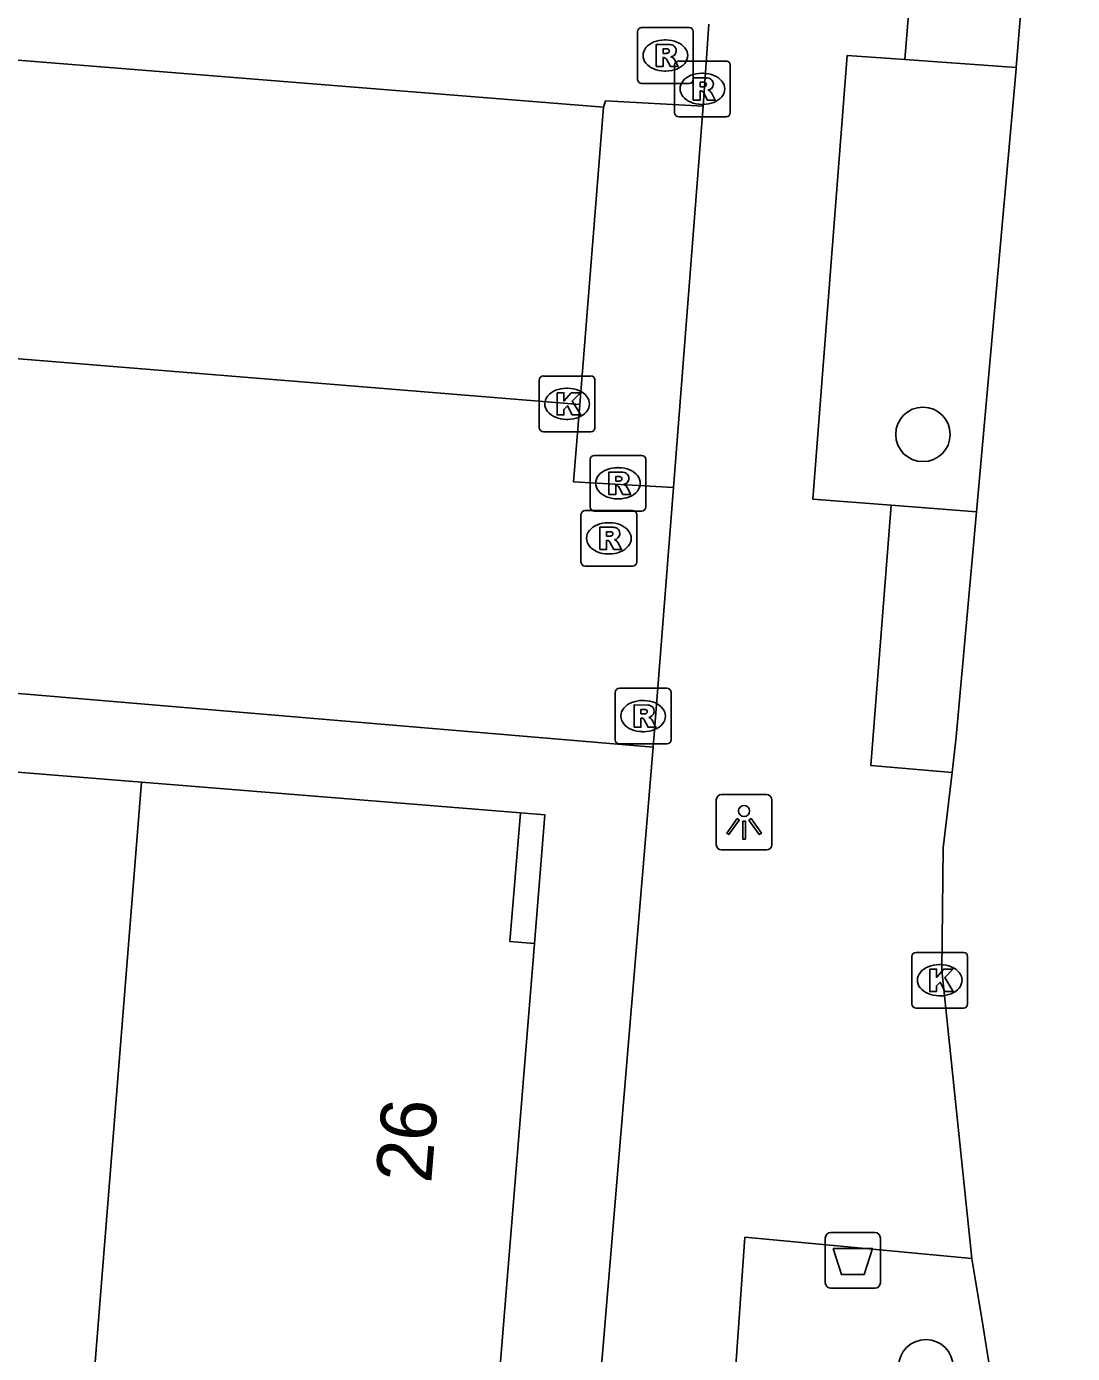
# Model space of a CAD drawing. Extents: x 159961 to 160856, y 382704 to 383353.
# Drawn here: x 160570.73 to 160589.51, y 383225.38 to 383249.21 of the extents above; entities that cross this region are included whole.
import ezdxf

# ---------------------------------------------------------------- set-up
doc = ezdxf.new("R2010")
doc.units = 0
for name, color, linetype in [('IMGEO_Afvalbak', 7, 'Continuous'), ('IMGEO_Boom', 7, 'Continuous'), ('IMGEO_Groenvoorziening', 7, 'Continuous'), ('IMGEO_Kolk', 7, 'Continuous'), ('IMGEO_Lichtpunt', 7, 'Continuous'), ('IMGEO_Pand', 7, 'Continuous'), ('IMGEO_Pand_nummerreeks', 7, 'Continuous'), ('IMGEO_Pand_overbouw', 7, 'Continuous'), ('IMGEO_Parkeervlak_open', 7, 'Continuous'), ('IMGEO_Rijbaan_lokaal_open', 7, 'Continuous'), ('IMGEO_Rioolput', 7, 'Continuous'), ('IMGEO_Voetpad_open', 7, 'Continuous')]:
    doc.layers.add(name, color=color, linetype=linetype)

msp = doc.modelspace()

# ---------------------------------------------------------------- linework, layer by layer
at = {"layer": 'IMGEO_Afvalbak'}
for p, q in [((160585.07, 383226.656), (160585.07, 383227.456)), ((160585.07, 383227.456), (160585.07, 383226.656)), ((160585.17, 383227.556), (160585.96, 383227.556)), ((160585.96, 383227.556), (160585.17, 383227.556)), ((160586.06, 383227.456), (160586.06, 383226.656)), ((160586.06, 383226.656), (160586.06, 383227.456)), ((160585.96, 383226.556), (160585.17, 383226.556)), ((160585.17, 383226.556), (160585.96, 383226.556))]:
    msp.add_line(p, q, dxfattribs=at)
msp.add_lwpolyline([(160585.213, 383227.27), (160585.917, 383227.27), (160585.768, 383226.8), (160585.362, 383226.8), (160585.213, 383227.27)], dxfattribs=at)
for centre, start, end in [((160585.17, 383227.456), 90, 180), ((160585.17, 383227.456), 90, 180), ((160585.96, 383227.456), 0, 90), ((160585.96, 383227.456), 360, 90), ((160585.17, 383226.656), 180, 270), ((160585.17, 383226.656), 180, 270), ((160585.96, 383226.656), 270, 0), ((160585.96, 383226.656), 270, 0)]:
    msp.add_arc(centre, 0.1, start, end, dxfattribs=at)
at = {"layer": 'IMGEO_Boom'}
for centre in [(160586.823, 383241.888), (160586.876, 383225.145)]:
    msp.add_circle(centre, 0.489, dxfattribs=at)
at = {"layer": 'IMGEO_Groenvoorziening'}
msp.add_lwpolyline([(160586.496, 383248.621), (160588.498, 383248.477)], dxfattribs=at)
at = {"layer": 'IMGEO_Kolk'}
for p, q in [((160579.934, 383242.011), (160579.934, 383242.863)), ((160580.009, 383242.937), (160580.861, 383242.937)), ((160580.935, 383242.863), (160580.935, 383242.011)), ((160580.422, 383242.717), (160580.447, 383242.717)), ((160580.445, 383242.157), (160580.42, 383242.157)), ((160580.861, 383241.937), (160580.009, 383241.937)), ((160586.699, 383232.587), (160587.551, 383232.587)), ((160586.624, 383231.661), (160586.624, 383232.513)), ((160587.112, 383232.367), (160587.137, 383232.367)), ((160587.625, 383232.513), (160587.625, 383231.661)), ((160587.135, 383231.807), (160587.11, 383231.807)), ((160587.551, 383231.587), (160586.699, 383231.587))]:
    msp.add_line(p, q, dxfattribs=at)
for points in [[(160579.934, 383242.011), (160579.934, 383242.863)], [(160580.009, 383242.937), (160580.861, 383242.937)], [(160580.935, 383242.863), (160580.935, 383242.011)], [(160580.255, 383242.637), (160580.378, 383242.637), (160580.378, 383242.486), (160580.508, 383242.637), (160580.672, 383242.637), (160580.526, 383242.486), (160580.679, 383242.237), (160580.527, 383242.237), (160580.442, 383242.401), (160580.378, 383242.334), (160580.378, 383242.237), (160580.255, 383242.237), (160580.255, 383242.637)], [(160580.861, 383241.937), (160580.009, 383241.937)], [(160586.699, 383232.587), (160587.551, 383232.587)], [(160586.624, 383231.661), (160586.624, 383232.513)], [(160587.625, 383232.513), (160587.625, 383231.661)], [(160586.945, 383232.287), (160587.068, 383232.287), (160587.068, 383232.136), (160587.198, 383232.287), (160587.362, 383232.287), (160587.216, 383232.136), (160587.369, 383231.887), (160587.217, 383231.887), (160587.132, 383232.051), (160587.068, 383231.984), (160587.068, 383231.887), (160586.945, 383231.887), (160586.945, 383232.287)], [(160587.551, 383231.587), (160586.699, 383231.587)]]:
    msp.add_lwpolyline(points, dxfattribs=at)
for centre, start, end in [((160580.011, 383242.861), 91.552, 178.448), ((160580.011, 383242.861), 91.552, 178.448), ((160580.859, 383242.861), 1.552, 88.448), ((160580.859, 383242.861), 1.552, 88.448), ((160580.011, 383242.013), 181.552, 268.448), ((160580.011, 383242.013), 181.552, 268.448), ((160580.859, 383242.013), 271.552, 358.448), ((160580.859, 383242.013), 271.552, 358.448), ((160586.701, 383232.511), 91.552, 178.448), ((160586.701, 383232.511), 91.552, 178.448), ((160587.549, 383232.511), 1.552, 88.448), ((160587.549, 383232.511), 1.552, 88.448), ((160586.701, 383231.663), 181.552, 268.448), ((160586.701, 383231.663), 181.552, 268.448), ((160587.549, 383231.663), 271.552, 358.448), ((160587.549, 383231.663), 271.552, 358.448)]:
    msp.add_arc(centre, 0.0765, start, end, dxfattribs=at)
for centre, major_axis, ratio, start_param, end_param in [((160580.421, 383242.437), (-0.387, 0.002), 0.722429, 4.712389, 7.853982), ((160580.446, 383242.437), (-0.39, 0.002), 0.717154, 1.570796, 4.712389), ((160587.111, 383232.087), (-0.387, 0.002), 0.722429, 4.712389, 7.853982), ((160587.136, 383232.087), (-0.39, 0.002), 0.717154, 1.570796, 4.712389)]:
    msp.add_ellipse(centre, major_axis=major_axis, ratio=ratio, start_param=start_param, end_param=end_param, dxfattribs=at)
at = {"layer": 'IMGEO_Lichtpunt'}
for p, q in [((160584.015, 383235.423), (160583.207, 383235.423)), ((160584.015, 383235.423), (160583.207, 383235.423)), ((160583.113, 383235.328), (160583.113, 383234.521)), ((160583.113, 383235.328), (160583.113, 383234.521)), ((160584.109, 383234.521), (160584.109, 383235.328)), ((160584.109, 383234.521), (160584.109, 383235.328)), ((160583.207, 383234.427), (160584.015, 383234.427)), ((160583.207, 383234.427), (160584.015, 383234.427))]:
    msp.add_line(p, q, dxfattribs=at)
for points in [[(160583.487, 383234.992), (160583.526, 383234.964), (160583.338, 383234.702), (160583.3, 383234.729), (160583.487, 383234.992)], [(160583.589, 383234.944), (160583.636, 383234.944), (160583.636, 383234.622), (160583.589, 383234.622), (160583.589, 383234.944)], [(160583.699, 383234.964), (160583.737, 383234.991), (160583.924, 383234.729), (160583.885, 383234.701), (160583.699, 383234.964)]]:
    msp.add_lwpolyline(points, dxfattribs=at)
msp.add_circle((160583.612, 383235.126), 0.0994, dxfattribs=at)
for centre, start, end in [((160583.207, 383235.328), 90, 180), ((160583.207, 383235.328), 90, 180), ((160584.015, 383235.328), 0, 90), ((160584.015, 383235.328), 0, 90), ((160583.207, 383234.521), 180, 270), ((160583.207, 383234.521), 180, 270), ((160584.015, 383234.521), 270, 0), ((160584.015, 383234.521), 270, 360)]:
    msp.add_arc(centre, 0.0946, start, end, dxfattribs=at)
at = {"layer": 'IMGEO_Pand'}
for points in [[(160571.829, 383223.583), (160572.795, 383235.644)], [(160572.795, 383235.644), (160574.348, 383235.518), (160579.597, 383235.091), (160579.407, 383232.783), (160579.849, 383232.745), (160579.226, 383225.088), (160578.784, 383225.124), (160578.614, 383223.032)]]:
    msp.add_lwpolyline(points, dxfattribs=at)
at = {"layer": 'IMGEO_Pand_overbouw'}
msp.add_lwpolyline([(160579.849, 383232.745), (160580.036, 383235.055), (160579.597, 383235.091), (160579.407, 383232.783)], close=True, dxfattribs=at)
at = {"layer": 'IMGEO_Parkeervlak_open'}
msp.add_lwpolyline([(160581.09, 383247.766), (160580.663, 383242.423)], dxfattribs=at)
at = {"layer": 'IMGEO_Rijbaan_lokaal_open'}
for points in [[(160589.508, 383260.177), (160588.952, 383254.011), (160588.498, 383248.477)], [(160588.498, 383248.477), (160588.496, 383248.453), (160587.783, 383240.496)], [(160568.236, 383243.436), (160580.663, 383242.423)], [(160581.98, 383236.274), (160570.304, 383237.257), (160570.385, 383238.185), (160570.07, 383238.212), (160565.614, 383238.538), (160510.942, 383242.971)], [(160580.663, 383242.423), (160580.551, 383241.038), (160582.344, 383240.936)], [(160582.344, 383240.936), (160581.98, 383236.274)], [(160587.783, 383240.496), (160587.421, 383236.457), (160587.346, 383235.819)], [(160587.701, 383227.093), (160587.161, 383232.265), (160587.185, 383234.463), (160587.346, 383235.819)], [(160588.179, 383224.135), (160587.897, 383225.898), (160587.701, 383227.093)]]:
    msp.add_lwpolyline(points, dxfattribs=at)
at = {"layer": 'IMGEO_Rioolput'}
for p, q in [((160581.698, 383248.266), (160581.698, 383249.118)), ((160581.773, 383249.192), (160582.625, 383249.192)), ((160582.699, 383249.118), (160582.699, 383248.266)), ((160582.186, 383248.972), (160582.211, 383248.972)), ((160582.438, 383248.593), (160583.29, 383248.593)), ((160582.209, 383248.412), (160582.184, 383248.412)), ((160582.363, 383247.667), (160582.363, 383248.519)), ((160582.851, 383248.373), (160582.876, 383248.373)), ((160583.364, 383248.519), (160583.364, 383247.667)), ((160582.625, 383248.192), (160581.773, 383248.192)), ((160582.874, 383247.813), (160582.849, 383247.813)), ((160583.29, 383247.593), (160582.438, 383247.593)), ((160580.847, 383240.585), (160580.847, 383241.437)), ((160580.922, 383241.511), (160581.774, 383241.511)), ((160581.848, 383241.437), (160581.848, 383240.585)), ((160581.335, 383241.291), (160581.36, 383241.291)), ((160581.358, 383240.731), (160581.333, 383240.731)), ((160580.683, 383239.596), (160580.683, 383240.448)), ((160580.758, 383240.522), (160581.61, 383240.522)), ((160581.774, 383240.511), (160580.922, 383240.511)), ((160581.684, 383240.448), (160581.684, 383239.596)), ((160581.171, 383240.302), (160581.196, 383240.302)), ((160581.194, 383239.742), (160581.169, 383239.742)), ((160581.61, 383239.522), (160580.758, 383239.522)), ((160581.374, 383237.33), (160582.226, 383237.33)), ((160581.299, 383236.404), (160581.299, 383237.256)), ((160581.787, 383237.11), (160581.812, 383237.11)), ((160582.3, 383237.256), (160582.3, 383236.404)), ((160581.81, 383236.55), (160581.785, 383236.55)), ((160582.226, 383236.33), (160581.374, 383236.33))]:
    msp.add_line(p, q, dxfattribs=at)
for points in [[(160581.698, 383248.266), (160581.698, 383249.118)], [(160581.773, 383249.192), (160582.625, 383249.192)], [(160582.699, 383249.118), (160582.699, 383248.266)], [(160582.287, 383248.89), (160582.035, 383248.892), (160582.035, 383248.492)], [(160582.213, 383248.811), (160582.159, 383248.811), (160582.159, 383248.73)], [(160582.035, 383248.492), (160582.159, 383248.492), (160582.159, 383248.654), (160582.17, 383248.654)], [(160582.159, 383248.73), (160582.211, 383248.73)], [(160582.217, 383248.625), (160582.288, 383248.492), (160582.428, 383248.492), (160582.363, 383248.618)], [(160582.438, 383248.593), (160583.29, 383248.593)], [(160582.363, 383247.667), (160582.363, 383248.519)], [(160582.952, 383248.291), (160582.7, 383248.293), (160582.7, 383247.893)], [(160583.364, 383248.519), (160583.364, 383247.667)], [(160582.625, 383248.192), (160581.773, 383248.192)], [(160582.7, 383247.893), (160582.824, 383247.893), (160582.824, 383248.055), (160582.835, 383248.055)], [(160582.878, 383248.212), (160582.824, 383248.212), (160582.824, 383248.131)], [(160582.824, 383248.131), (160582.876, 383248.131)], [(160582.882, 383248.026), (160582.953, 383247.893), (160583.093, 383247.893), (160583.028, 383248.019)], [(160583.29, 383247.593), (160582.438, 383247.593)], [(160580.847, 383240.585), (160580.847, 383241.437)], [(160580.922, 383241.511), (160581.774, 383241.511)], [(160581.848, 383241.437), (160581.848, 383240.585)], [(160581.436, 383241.209), (160581.184, 383241.211), (160581.184, 383240.811)], [(160581.184, 383240.811), (160581.308, 383240.811), (160581.308, 383240.973), (160581.319, 383240.973)], [(160581.362, 383241.13), (160581.308, 383241.13), (160581.308, 383241.049)], [(160581.308, 383241.049), (160581.36, 383241.049)], [(160581.366, 383240.944), (160581.437, 383240.811), (160581.577, 383240.811), (160581.512, 383240.937)], [(160580.683, 383239.596), (160580.683, 383240.448)], [(160580.758, 383240.522), (160581.61, 383240.522)], [(160581.774, 383240.511), (160580.922, 383240.511)], [(160581.684, 383240.448), (160581.684, 383239.596)], [(160581.272, 383240.22), (160581.02, 383240.222), (160581.02, 383239.822)], [(160581.02, 383239.822), (160581.144, 383239.822), (160581.144, 383239.984), (160581.155, 383239.984)], [(160581.198, 383240.141), (160581.144, 383240.141), (160581.144, 383240.06)], [(160581.144, 383240.06), (160581.196, 383240.06)], [(160581.202, 383239.955), (160581.273, 383239.822), (160581.413, 383239.822), (160581.348, 383239.948)], [(160581.61, 383239.522), (160580.758, 383239.522)], [(160581.374, 383237.33), (160582.226, 383237.33)], [(160581.299, 383236.404), (160581.299, 383237.256)], [(160582.3, 383237.256), (160582.3, 383236.404)], [(160581.888, 383237.028), (160581.636, 383237.03), (160581.636, 383236.63)], [(160581.814, 383236.949), (160581.76, 383236.949), (160581.76, 383236.868)], [(160581.76, 383236.868), (160581.812, 383236.868)], [(160581.636, 383236.63), (160581.76, 383236.63), (160581.76, 383236.792), (160581.771, 383236.792)], [(160581.818, 383236.763), (160581.889, 383236.63), (160582.029, 383236.63), (160581.964, 383236.756)], [(160582.226, 383236.33), (160581.374, 383236.33)]]:
    msp.add_lwpolyline(points, dxfattribs=at)
for centre, radius, start, end in [((160581.775, 383249.116), 0.0765, 91.552, 178.448), ((160581.775, 383249.116), 0.0765, 91.552, 178.448), ((160582.623, 383249.116), 0.0765, 1.552, 88.448), ((160582.623, 383249.116), 0.0765, 1.552, 88.448), ((160582.219, 383248.715), 0.0964, 77.0061, 93.1865), ((160582.233, 383248.772), 0.0378, 276.6634, 79.6772), ((160582.286, 383248.78), 0.109, 350.3612, 89.416), ((160582.169, 383248.601), 0.0533, 26.0293, 88.6989), ((160582.195, 383248.919), 0.19, 274.7715, 282.9687), ((160582.284, 383248.78), 0.112, 277.5842, 350.9817), ((160582.268, 383248.565), 0.108, 29.5134, 73.7905), ((160582.44, 383248.517), 0.0765, 91.552, 178.448), ((160582.44, 383248.517), 0.0765, 91.552, 178.448), ((160583.288, 383248.517), 0.0765, 1.552, 88.448), ((160583.288, 383248.517), 0.0765, 1.552, 88.448), ((160582.951, 383248.181), 0.109, 350.3612, 89.416), ((160581.775, 383248.268), 0.0765, 181.552, 268.448), ((160581.775, 383248.268), 0.0765, 181.552, 268.448), ((160582.623, 383248.268), 0.0765, 271.552, 358.448), ((160582.623, 383248.268), 0.0765, 271.552, 358.448), ((160582.834, 383248.002), 0.0533, 26.0293, 88.6989), ((160582.86, 383248.32), 0.19, 274.7715, 282.9687), ((160582.884, 383248.116), 0.0964, 77.0061, 93.1865), ((160582.898, 383248.173), 0.0378, 276.6634, 79.6772), ((160582.949, 383248.181), 0.112, 277.5842, 350.9817), ((160582.933, 383247.966), 0.108, 29.5134, 73.7905), ((160582.44, 383247.669), 0.0765, 181.552, 268.448), ((160582.44, 383247.669), 0.0765, 181.552, 268.448), ((160583.288, 383247.669), 0.0765, 271.552, 358.448), ((160583.288, 383247.669), 0.0765, 271.552, 358.448), ((160580.924, 383241.435), 0.0765, 91.552, 178.448), ((160580.924, 383241.435), 0.0765, 91.552, 178.448), ((160581.772, 383241.435), 0.0765, 1.552, 88.448), ((160581.772, 383241.435), 0.0765, 1.552, 88.448), ((160581.435, 383241.099), 0.109, 350.3612, 89.416), ((160581.318, 383240.92), 0.0533, 26.0293, 88.6989), ((160581.344, 383241.238), 0.19, 274.7715, 282.9687), ((160581.368, 383241.034), 0.0964, 77.0061, 93.1865), ((160581.382, 383241.091), 0.0378, 276.6634, 79.6772), ((160581.433, 383241.099), 0.112, 277.5842, 350.9817), ((160581.417, 383240.884), 0.108, 29.5134, 73.7905), ((160580.76, 383240.446), 0.0765, 91.552, 178.448), ((160580.76, 383240.446), 0.0765, 91.552, 178.448), ((160580.924, 383240.587), 0.0765, 181.552, 268.448), ((160580.924, 383240.587), 0.0765, 181.552, 268.448), ((160581.608, 383240.446), 0.0765, 1.552, 88.448), ((160581.608, 383240.446), 0.0765, 1.552, 88.448), ((160581.772, 383240.587), 0.0765, 271.552, 358.448), ((160581.772, 383240.587), 0.0765, 271.552, 358.448), ((160581.271, 383240.11), 0.109, 350.3612, 89.416), ((160581.154, 383239.931), 0.0533, 26.0293, 88.6989), ((160581.18, 383240.249), 0.19, 274.7715, 282.9687), ((160581.204, 383240.045), 0.0964, 77.0061, 93.1865), ((160581.218, 383240.102), 0.0378, 276.6634, 79.6772), ((160581.269, 383240.11), 0.112, 277.5842, 350.9817), ((160581.253, 383239.895), 0.108, 29.5134, 73.7905), ((160580.76, 383239.598), 0.0765, 181.552, 268.448), ((160580.76, 383239.598), 0.0765, 181.552, 268.448), ((160581.608, 383239.598), 0.0765, 271.552, 358.448), ((160581.608, 383239.598), 0.0765, 271.552, 358.448), ((160581.376, 383237.254), 0.0765, 91.552, 178.448), ((160581.376, 383237.254), 0.0765, 91.552, 178.448), ((160582.224, 383237.254), 0.0765, 1.552, 88.448), ((160582.224, 383237.254), 0.0765, 1.552, 88.448), ((160581.796, 383237.057), 0.19, 274.7715, 282.9687), ((160581.82, 383236.853), 0.0964, 77.0061, 93.1865), ((160581.834, 383236.91), 0.0378, 276.6634, 79.6772), ((160581.887, 383236.918), 0.109, 350.3612, 89.416), ((160581.885, 383236.918), 0.112, 277.5842, 350.9817), ((160581.77, 383236.739), 0.0533, 26.0293, 88.6989), ((160581.869, 383236.703), 0.108, 29.5134, 73.7905), ((160581.376, 383236.406), 0.0765, 181.552, 268.448), ((160581.376, 383236.406), 0.0765, 181.552, 268.448), ((160582.224, 383236.406), 0.0765, 271.552, 358.448), ((160582.224, 383236.406), 0.0765, 271.552, 358.448)]:
    msp.add_arc(centre, radius, start, end, dxfattribs=at)
for centre, major_axis, ratio, start_param, end_param in [((160582.185, 383248.692), (-0.387, 0.002), 0.722429, 4.712389, 7.853982), ((160582.21, 383248.692), (-0.39, 0.002), 0.717154, 1.570796, 4.712389), ((160582.85, 383248.093), (-0.387, 0.002), 0.722429, 4.712389, 7.853982), ((160582.875, 383248.093), (-0.39, 0.002), 0.717154, 1.570796, 4.712389), ((160581.334, 383241.011), (-0.387, 0.002), 0.722429, 4.712389, 7.853982), ((160581.359, 383241.011), (-0.39, 0.002), 0.717154, 1.570796, 4.712389), ((160581.17, 383240.022), (-0.387, 0.002), 0.722429, 4.712389, 7.853982), ((160581.195, 383240.022), (-0.39, 0.002), 0.717154, 1.570796, 4.712389), ((160581.786, 383236.83), (-0.387, 0.002), 0.722429, 4.712389, 7.853982), ((160581.811, 383236.83), (-0.39, 0.002), 0.717154, 1.570796, 4.712389)]:
    msp.add_ellipse(centre, major_axis=major_axis, ratio=ratio, start_param=start_param, end_param=end_param, dxfattribs=at)
at = {"layer": 'IMGEO_Voetpad_open'}
for points in [[(160586.496, 383248.621), (160587.457, 383260.35), (160589.508, 383260.177)], [(160582.981, 383249.253), (160582.88, 383247.781)], [(160581.09, 383247.766), (160568.629, 383248.766)], [(160586.253, 383240.615), (160584.847, 383240.724), (160585.463, 383248.695), (160586.496, 383248.621)], [(160582.88, 383247.781), (160581.126, 383247.88), (160581.09, 383247.766)], [(160582.88, 383247.781), (160582.344, 383240.936)], [(160587.346, 383235.819), (160585.886, 383235.943), (160586.253, 383240.615)], [(160587.783, 383240.496), (160586.253, 383240.615)], [(160581.98, 383236.274), (160579.082, 383201.597), (160578.819, 383198.623)], [(160572.795, 383235.644), (160570.19, 383235.856), (160569.944, 383235.876), (160569.472, 383229.98), (160569.438, 383232.935)], [(160583.342, 383223.457), (160583.628, 383227.471), (160587.701, 383227.093)]]:
    msp.add_lwpolyline(points, dxfattribs=at)

# ---------------------------------------------------------------- texts
at = {"layer": 'IMGEO_Pand_nummerreeks'}
msp.add_text('26', height=1, rotation=85.3478, dxfattribs=at).set_placement((160577.993, 383228.428))

doc.saveas('drawing.dxf')
